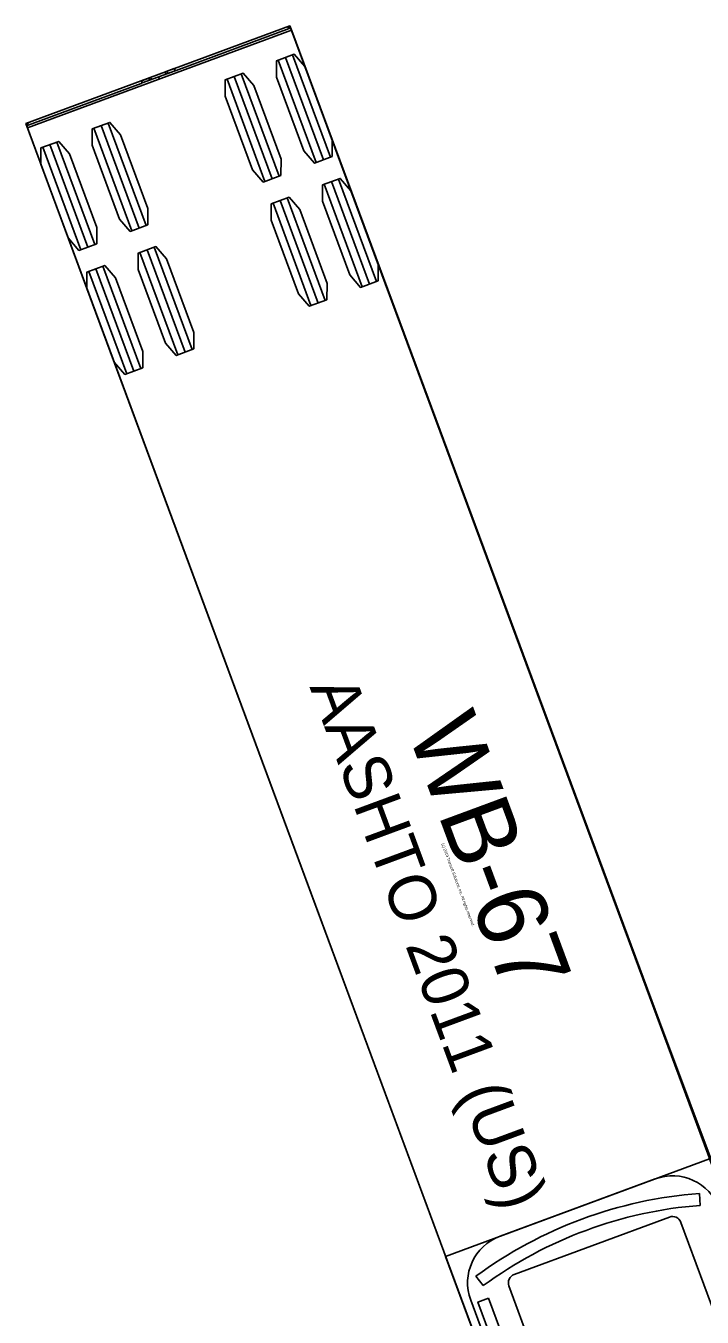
# Model space of a CAD drawing. Extents: x 1639988 to 1641860, y 841974 to 844187.
# Drawn here: x 1640169.79 to 1640190.21, y 844148.44 to 844187.46 of the extents above; entities that cross this region are included whole.
import ezdxf

# ---------------------------------------------------------------- set-up
doc = ezdxf.new("R2010")
doc.units = 0
for name, color, linetype in [('Scratch_Level_1', 7, 'Continuous'), ('Scratch_Level_2', 7, 'Continuous'), ('Scratch_Level_3', 7, 'Continuous'), ('Scratch_Level_4', 7, 'Continuous'), ('Scratch_Level_5', 7, 'Continuous'), ('Scratch_Level_6', 7, 'Continuous')]:
    doc.layers.add(name, color=color, linetype=linetype)

msp = doc.modelspace()

# ---------------------------------------------------------------- linework, layer by layer
at = {"layer": 'Scratch_Level_1'}
for p, q in [((1640169.838, 844184.375), (1640177.809, 844187.327)), ((1640178.556, 844183.329), (1640177.41, 844186.423)), ((1640178.771, 844183.408), (1640177.625, 844186.503)), ((1640178.986, 844183.488), (1640177.84, 844186.583)), ((1640174.048, 844186.01), (1640174.297, 844186.102)), ((1640177.224, 844182.835), (1640176.078, 844185.93)), ((1640177.439, 844182.915), (1640176.293, 844186.01)), ((1640173.301, 844185.733), (1640173.55, 844185.825)), ((1640173.799, 844185.917), (1640173.824, 844185.851)), ((1640177.009, 844182.756), (1640175.863, 844185.85)), ((1640173.207, 844181.348), (1640172.061, 844184.443)), ((1640173.422, 844181.428), (1640172.276, 844184.522)), ((1640172.992, 844181.269), (1640171.846, 844184.363)), ((1640171.445, 844180.696), (1640170.299, 844183.79)), ((1640171.66, 844180.775), (1640170.514, 844183.87)), ((1640171.875, 844180.855), (1640170.729, 844183.949)), ((1640180.375, 844179.737), (1640179.229, 844182.831)), ((1640179.945, 844179.578), (1640178.799, 844182.672)), ((1640180.16, 844179.657), (1640179.014, 844182.752)), ((1640178.398, 844179.005), (1640177.252, 844182.099)), ((1640178.613, 844179.084), (1640177.467, 844182.179)), ((1640178.828, 844179.164), (1640177.682, 844182.258)), ((1640174.381, 844177.517), (1640173.235, 844180.612)), ((1640174.596, 844177.597), (1640173.45, 844180.692)), ((1640174.811, 844177.677), (1640173.665, 844180.771)), ((1640173.049, 844177.024), (1640171.903, 844180.119)), ((1640173.263, 844177.104), (1640172.118, 844180.198)), ((1640172.834, 844176.944), (1640171.688, 844180.039))]:
    msp.add_line(p, q, dxfattribs=at)
for points in [[(1640240.487, 843983.993), (1640239.855, 843986.609), (1640227.577, 844027.488), (1640224.497, 844037.651), (1640222.927, 844042.709), (1640221.325, 844047.747), (1640219.681, 844052.761), (1640217.992, 844057.753), (1640216.257, 844062.717), (1640214.476, 844067.667), (1640212.652, 844072.609), (1640208.555, 844082.348), (1640206.537, 844087.24), (1640204.541, 844092.149), (1640202.565, 844097.075), (1640200.611, 844102.018), (1640198.676, 844106.976), (1640196.761, 844111.949), (1640192.983, 844121.925), (1640185.677, 844141.598), (1640169.789, 844184.508), (1640177.76, 844187.459), (1640177.815, 844187.311), (1640177.815, 844187.311)], [(1640169.834, 844184.449), (1640169.814, 844184.442), (1640169.839, 844184.376), (1640171.806, 844179.061), (1640188.192, 844134.805), (1640192.177, 844136.281), (1640196.163, 844137.757), (1640179.777, 844182.012), (1640177.808, 844187.327), (1640177.784, 844187.393), (1640177.764, 844187.385)], [(1640177.741, 844187.377), (1640177.74, 844187.377), (1640174.331, 844186.114), (1640174.297, 844186.102), (1640174.273, 844186.167), (1640174.271, 844186.167), (1640174.021, 844186.075)], [(1640177.815, 844187.311), (1640188.919, 844157.376), (1640192.648, 844147.427), (1640196.411, 844137.497), (1640200.22, 844127.592), (1640204.089, 844117.705), (1640228.263, 844057.033)], [(1640174.042, 844186.007), (1640173.553, 844185.826)], [(1640173.528, 844185.892), (1640173.278, 844185.8), (1640173.276, 844185.799), (1640173.301, 844185.733), (1640173.267, 844185.72), (1640169.858, 844184.458), (1640169.857, 844184.458)]]:
    msp.add_lwpolyline(points, dxfattribs=at)
for points in [[(1640179.039, 844183.508), (1640178.503, 844183.309), (1640178.181, 844183.682), (1640177.356, 844185.911), (1640177.357, 844186.404), (1640177.894, 844186.602), (1640178.216, 844186.229), (1640179.041, 844184.001)], [(1640177.492, 844182.935), (1640176.956, 844182.736), (1640176.634, 844183.109), (1640175.809, 844185.338), (1640175.81, 844185.831), (1640176.346, 844186.029), (1640176.668, 844185.656), (1640177.493, 844183.428)], [(1640173.475, 844181.447), (1640172.939, 844181.249), (1640172.617, 844181.622), (1640171.792, 844183.85), (1640171.793, 844184.343), (1640172.329, 844184.542), (1640172.651, 844184.169), (1640173.476, 844181.94)], [(1640171.928, 844180.874), (1640171.391, 844180.676), (1640171.069, 844181.049), (1640170.244, 844183.277), (1640170.246, 844183.771), (1640170.782, 844183.969), (1640171.104, 844183.596), (1640171.929, 844181.368)], [(1640180.428, 844179.756), (1640179.892, 844179.558), (1640179.57, 844179.931), (1640178.745, 844182.159), (1640178.746, 844182.653), (1640179.282, 844182.851), (1640179.605, 844182.478), (1640180.43, 844180.25)], [(1640178.881, 844179.184), (1640178.345, 844178.985), (1640178.023, 844179.358), (1640177.198, 844181.587), (1640177.199, 844182.08), (1640177.735, 844182.278), (1640178.057, 844181.905), (1640178.882, 844179.677)], [(1640174.864, 844177.696), (1640174.328, 844177.498), (1640174.006, 844177.871), (1640173.181, 844180.099), (1640173.182, 844180.592), (1640173.718, 844180.791), (1640174.04, 844180.418), (1640174.865, 844178.189)], [(1640173.317, 844177.123), (1640172.78, 844176.925), (1640172.458, 844177.298), (1640171.633, 844179.526), (1640171.635, 844180.019), (1640172.171, 844180.218), (1640172.493, 844179.845), (1640173.318, 844177.616)]]:
    msp.add_lwpolyline(points, close=True, dxfattribs=at)
for centre in [(1640177.741, 844187.413), (1640169.834, 844184.486)]:
    msp.add_circle(centre, 0.0266, dxfattribs=at)
for centre, radius, start, end in [((1640177.741, 844187.413), 0.0363, 309.395, 270.5563), ((1640174.033, 844186.042), 0.0352, 110.3428, 289.3432), ((1640174.034, 844186.042), 0.0353, 293.6537, 112.0033), ((1640173.54, 844185.859), 0.0354, 114.609, 286.7945), ((1640173.54, 844185.859), 0.0352, 291.2918, 110.2922), ((1640169.132, 844186.345), 2.022, 290.3175, 291.0013)]:
    msp.add_arc(centre, radius, start, end, dxfattribs=at)
at = {"layer": 'Scratch_Level_2'}
for p, q in [((1640169.838, 844184.375), (1640177.809, 844187.327)), ((1640178.556, 844183.329), (1640177.41, 844186.423)), ((1640178.771, 844183.408), (1640177.625, 844186.503)), ((1640178.986, 844183.488), (1640177.84, 844186.583)), ((1640174.048, 844186.01), (1640174.297, 844186.102)), ((1640177.224, 844182.835), (1640176.078, 844185.93)), ((1640177.439, 844182.915), (1640176.293, 844186.01)), ((1640173.301, 844185.733), (1640173.55, 844185.825)), ((1640173.799, 844185.917), (1640173.824, 844185.851)), ((1640177.009, 844182.756), (1640175.863, 844185.85)), ((1640173.207, 844181.348), (1640172.061, 844184.443)), ((1640173.422, 844181.428), (1640172.276, 844184.522)), ((1640172.992, 844181.269), (1640171.846, 844184.363)), ((1640171.445, 844180.696), (1640170.299, 844183.79)), ((1640171.66, 844180.775), (1640170.514, 844183.87)), ((1640171.875, 844180.855), (1640170.729, 844183.949)), ((1640180.375, 844179.737), (1640179.229, 844182.831)), ((1640179.945, 844179.578), (1640178.799, 844182.672)), ((1640180.16, 844179.657), (1640179.014, 844182.752)), ((1640178.398, 844179.005), (1640177.252, 844182.099)), ((1640178.613, 844179.084), (1640177.467, 844182.179)), ((1640178.828, 844179.164), (1640177.682, 844182.258)), ((1640174.381, 844177.517), (1640173.235, 844180.612)), ((1640174.596, 844177.597), (1640173.45, 844180.692)), ((1640174.811, 844177.677), (1640173.665, 844180.771)), ((1640173.049, 844177.024), (1640171.903, 844180.119)), ((1640173.263, 844177.104), (1640172.118, 844180.198)), ((1640172.834, 844176.944), (1640171.688, 844180.039))]:
    msp.add_line(p, q, dxfattribs=at)
for points in [[(1640240.487, 843983.993), (1640239.855, 843986.609), (1640227.577, 844027.488), (1640224.497, 844037.651), (1640222.927, 844042.709), (1640221.325, 844047.747), (1640219.681, 844052.761), (1640217.992, 844057.753), (1640216.257, 844062.717), (1640214.476, 844067.667), (1640212.652, 844072.609), (1640208.555, 844082.348), (1640206.537, 844087.24), (1640204.541, 844092.149), (1640202.565, 844097.075), (1640200.611, 844102.018), (1640198.676, 844106.976), (1640196.761, 844111.949), (1640192.983, 844121.925), (1640185.677, 844141.598), (1640169.789, 844184.508), (1640177.76, 844187.459), (1640177.811, 844187.321), (1640177.811, 844187.321)], [(1640169.834, 844184.449), (1640169.814, 844184.442), (1640169.839, 844184.376), (1640171.806, 844179.061), (1640188.192, 844134.805), (1640192.177, 844136.281), (1640196.163, 844137.757), (1640179.777, 844182.012), (1640177.808, 844187.327), (1640177.784, 844187.393), (1640177.764, 844187.385)], [(1640177.741, 844187.377), (1640177.74, 844187.377), (1640174.331, 844186.114), (1640174.297, 844186.102), (1640174.273, 844186.167), (1640174.271, 844186.167), (1640174.021, 844186.075)], [(1640177.811, 844187.321), (1640188.919, 844157.376), (1640192.648, 844147.427), (1640196.411, 844137.497), (1640200.22, 844127.592), (1640204.089, 844117.705), (1640228.263, 844057.033)], [(1640174.042, 844186.007), (1640173.553, 844185.826)], [(1640173.528, 844185.892), (1640173.278, 844185.8), (1640173.276, 844185.799), (1640173.301, 844185.733), (1640173.267, 844185.72), (1640169.858, 844184.458), (1640169.857, 844184.458)]]:
    msp.add_lwpolyline(points, dxfattribs=at)
for points in [[(1640179.039, 844183.508), (1640178.503, 844183.309), (1640178.181, 844183.682), (1640177.356, 844185.911), (1640177.357, 844186.404), (1640177.894, 844186.602), (1640178.216, 844186.229), (1640179.041, 844184.001)], [(1640177.492, 844182.935), (1640176.956, 844182.736), (1640176.634, 844183.109), (1640175.809, 844185.338), (1640175.81, 844185.831), (1640176.346, 844186.029), (1640176.668, 844185.656), (1640177.493, 844183.428)], [(1640173.475, 844181.447), (1640172.939, 844181.249), (1640172.617, 844181.622), (1640171.792, 844183.85), (1640171.793, 844184.343), (1640172.329, 844184.542), (1640172.651, 844184.169), (1640173.476, 844181.94)], [(1640171.928, 844180.874), (1640171.391, 844180.676), (1640171.069, 844181.049), (1640170.244, 844183.277), (1640170.246, 844183.771), (1640170.782, 844183.969), (1640171.104, 844183.596), (1640171.929, 844181.368)], [(1640180.428, 844179.756), (1640179.892, 844179.558), (1640179.57, 844179.931), (1640178.745, 844182.159), (1640178.746, 844182.653), (1640179.282, 844182.851), (1640179.605, 844182.478), (1640180.43, 844180.25)], [(1640178.881, 844179.184), (1640178.345, 844178.985), (1640178.023, 844179.358), (1640177.198, 844181.587), (1640177.199, 844182.08), (1640177.735, 844182.278), (1640178.057, 844181.905), (1640178.882, 844179.677)], [(1640174.864, 844177.696), (1640174.328, 844177.498), (1640174.006, 844177.871), (1640173.181, 844180.099), (1640173.182, 844180.592), (1640173.718, 844180.791), (1640174.04, 844180.418), (1640174.865, 844178.189)], [(1640173.317, 844177.123), (1640172.78, 844176.925), (1640172.458, 844177.298), (1640171.633, 844179.526), (1640171.635, 844180.019), (1640172.171, 844180.218), (1640172.493, 844179.845), (1640173.318, 844177.616)]]:
    msp.add_lwpolyline(points, close=True, dxfattribs=at)
for centre in [(1640177.741, 844187.413), (1640169.834, 844184.486)]:
    msp.add_circle(centre, 0.0266, dxfattribs=at)
for centre, radius, start, end in [((1640177.741, 844187.413), 0.0363, 309.395, 270.5563), ((1640174.033, 844186.042), 0.0352, 110.3428, 289.3432), ((1640174.034, 844186.042), 0.0353, 293.6537, 112.0033), ((1640173.54, 844185.859), 0.0354, 114.609, 286.7945), ((1640173.54, 844185.859), 0.0352, 291.2918, 110.2922), ((1640169.132, 844186.345), 2.022, 290.3175, 291.0013)]:
    msp.add_arc(centre, radius, start, end, dxfattribs=at)
at = {"layer": 'Scratch_Level_3'}
for p, q in [((1640169.838, 844184.375), (1640177.809, 844187.327)), ((1640178.556, 844183.329), (1640177.41, 844186.423)), ((1640178.771, 844183.408), (1640177.625, 844186.503)), ((1640178.986, 844183.488), (1640177.84, 844186.583)), ((1640174.048, 844186.01), (1640174.297, 844186.102)), ((1640177.224, 844182.835), (1640176.078, 844185.93)), ((1640177.439, 844182.915), (1640176.293, 844186.01)), ((1640173.301, 844185.733), (1640173.55, 844185.825)), ((1640173.799, 844185.917), (1640173.824, 844185.851)), ((1640177.009, 844182.756), (1640175.863, 844185.85)), ((1640173.207, 844181.348), (1640172.061, 844184.443)), ((1640173.422, 844181.428), (1640172.276, 844184.522)), ((1640172.992, 844181.269), (1640171.846, 844184.363)), ((1640171.445, 844180.696), (1640170.299, 844183.79)), ((1640171.66, 844180.775), (1640170.514, 844183.87)), ((1640171.875, 844180.855), (1640170.729, 844183.949)), ((1640180.375, 844179.737), (1640179.229, 844182.831)), ((1640179.945, 844179.578), (1640178.799, 844182.672)), ((1640180.16, 844179.657), (1640179.014, 844182.752)), ((1640178.398, 844179.005), (1640177.252, 844182.099)), ((1640178.613, 844179.084), (1640177.467, 844182.179)), ((1640178.828, 844179.164), (1640177.682, 844182.258)), ((1640174.381, 844177.517), (1640173.235, 844180.612)), ((1640174.596, 844177.597), (1640173.45, 844180.692)), ((1640174.811, 844177.677), (1640173.665, 844180.771)), ((1640173.049, 844177.024), (1640171.903, 844180.119)), ((1640173.263, 844177.104), (1640172.118, 844180.198)), ((1640172.834, 844176.944), (1640171.688, 844180.039))]:
    msp.add_line(p, q, dxfattribs=at)
for points in [[(1640240.487, 843983.993), (1640239.855, 843986.609), (1640227.577, 844027.488), (1640224.497, 844037.651), (1640222.927, 844042.709), (1640221.325, 844047.747), (1640219.681, 844052.761), (1640217.992, 844057.753), (1640216.257, 844062.717), (1640214.476, 844067.667), (1640212.652, 844072.609), (1640208.555, 844082.348), (1640206.537, 844087.24), (1640204.541, 844092.149), (1640202.565, 844097.075), (1640200.611, 844102.018), (1640198.676, 844106.976), (1640196.761, 844111.949), (1640192.983, 844121.925), (1640185.677, 844141.598), (1640169.789, 844184.508), (1640177.76, 844187.459), (1640177.809, 844187.326), (1640177.809, 844187.326)], [(1640169.834, 844184.449), (1640169.814, 844184.442), (1640169.839, 844184.376), (1640171.806, 844179.061), (1640188.192, 844134.805), (1640192.177, 844136.281), (1640196.163, 844137.757), (1640179.777, 844182.012), (1640177.808, 844187.327), (1640177.784, 844187.393), (1640177.764, 844187.385)], [(1640177.741, 844187.377), (1640177.74, 844187.377), (1640174.331, 844186.114), (1640174.297, 844186.102), (1640174.273, 844186.167), (1640174.271, 844186.167), (1640174.021, 844186.075)], [(1640177.809, 844187.326), (1640188.919, 844157.376), (1640192.648, 844147.427), (1640196.411, 844137.497), (1640200.22, 844127.592), (1640204.089, 844117.705), (1640228.263, 844057.033)], [(1640174.042, 844186.007), (1640173.553, 844185.826)], [(1640173.528, 844185.892), (1640173.278, 844185.8), (1640173.276, 844185.799), (1640173.301, 844185.733), (1640173.267, 844185.72), (1640169.858, 844184.458), (1640169.857, 844184.458)]]:
    msp.add_lwpolyline(points, dxfattribs=at)
for points in [[(1640179.039, 844183.508), (1640178.503, 844183.309), (1640178.181, 844183.682), (1640177.356, 844185.911), (1640177.357, 844186.404), (1640177.894, 844186.602), (1640178.216, 844186.229), (1640179.041, 844184.001)], [(1640177.492, 844182.935), (1640176.956, 844182.736), (1640176.634, 844183.109), (1640175.809, 844185.338), (1640175.81, 844185.831), (1640176.346, 844186.029), (1640176.668, 844185.656), (1640177.493, 844183.428)], [(1640173.475, 844181.447), (1640172.939, 844181.249), (1640172.617, 844181.622), (1640171.792, 844183.85), (1640171.793, 844184.343), (1640172.329, 844184.542), (1640172.651, 844184.169), (1640173.476, 844181.94)], [(1640171.928, 844180.874), (1640171.391, 844180.676), (1640171.069, 844181.049), (1640170.244, 844183.277), (1640170.246, 844183.771), (1640170.782, 844183.969), (1640171.104, 844183.596), (1640171.929, 844181.368)], [(1640180.428, 844179.756), (1640179.892, 844179.558), (1640179.57, 844179.931), (1640178.745, 844182.159), (1640178.746, 844182.653), (1640179.282, 844182.851), (1640179.605, 844182.478), (1640180.43, 844180.25)], [(1640178.881, 844179.184), (1640178.345, 844178.985), (1640178.023, 844179.358), (1640177.198, 844181.587), (1640177.199, 844182.08), (1640177.735, 844182.278), (1640178.057, 844181.905), (1640178.882, 844179.677)], [(1640174.864, 844177.696), (1640174.328, 844177.498), (1640174.006, 844177.871), (1640173.181, 844180.099), (1640173.182, 844180.592), (1640173.718, 844180.791), (1640174.04, 844180.418), (1640174.865, 844178.189)], [(1640173.317, 844177.123), (1640172.78, 844176.925), (1640172.458, 844177.298), (1640171.633, 844179.526), (1640171.635, 844180.019), (1640172.171, 844180.218), (1640172.493, 844179.845), (1640173.318, 844177.616)]]:
    msp.add_lwpolyline(points, close=True, dxfattribs=at)
for centre in [(1640177.741, 844187.413), (1640169.834, 844184.486)]:
    msp.add_circle(centre, 0.0266, dxfattribs=at)
for centre, radius, start, end in [((1640177.741, 844187.413), 0.0363, 309.395, 270.5563), ((1640174.033, 844186.042), 0.0352, 110.3428, 289.3432), ((1640174.034, 844186.042), 0.0353, 293.6537, 112.0033), ((1640173.54, 844185.859), 0.0354, 114.609, 286.7945), ((1640173.54, 844185.859), 0.0352, 291.2918, 110.2922), ((1640169.132, 844186.345), 2.022, 290.3175, 291.0013)]:
    msp.add_arc(centre, radius, start, end, dxfattribs=at)
at = {"layer": 'Scratch_Level_4'}
for p, q in [((1640189.218, 844151.469), (1640184.532, 844149.734)), ((1640202.216, 844117.144), (1640189.566, 844151.309)), ((1640184.372, 844149.386), (1640197.022, 844115.221))]:
    msp.add_line(p, q, dxfattribs=at)
for points in [[(1640207.65, 844083.889), (1640205.634, 844088.831), (1640203.645, 844093.787), (1640201.686, 844098.755), (1640199.758, 844103.733), (1640197.861, 844108.723), (1640182.463, 844150.279), (1640190.434, 844153.23), (1640190.54, 844152.943), (1640190.54, 844152.943)], [(1640188.791, 844152.622), (1640184.105, 844150.887)], [(1640190.126, 844152.182), (1640190.147, 844151.821)], [(1640183.598, 844149.396), (1640183.379, 844149.683)], [(1640183.219, 844148.959), (1640184.819, 844144.639), (1640184.633, 844144.418), (1640185.848, 844141.135), (1640186.133, 844141.088), (1640193.443, 844121.345), (1640193.313, 844120.973), (1640194.528, 844117.691), (1640194.869, 844117.493)]]:
    msp.add_lwpolyline(points, dxfattribs=at)
msp.add_lwpolyline([(1640183.76, 844149.019), (1640183.437, 844148.9), (1640185.506, 844143.31), (1640185.829, 844143.431)], close=True, dxfattribs=at)
for centre, radius, start, end in [((1640189.312, 844151.215), 1.5, 20.3175, 110.3175), ((1640191.116, 844139.147), 13.073, 94.3446, 126.2904), ((1640191.116, 844139.147), 12.711, 94.3748, 126.2603), ((1640189.312, 844151.215), 0.27, 20.3175, 110.3175), ((1640184.626, 844149.48), 1.5, 110.3175, 200.3175), ((1640184.626, 844149.48), 0.27, 110.3175, 200.3175)]:
    msp.add_arc(centre, radius, start, end, dxfattribs=at)
at = {"layer": 'Scratch_Level_5'}
for p, q in [((1640189.218, 844151.469), (1640184.532, 844149.734)), ((1640202.216, 844117.144), (1640189.566, 844151.309)), ((1640184.372, 844149.386), (1640197.022, 844115.221))]:
    msp.add_line(p, q, dxfattribs=at)
for points in [[(1640207.65, 844083.889), (1640205.634, 844088.831), (1640203.645, 844093.787), (1640201.686, 844098.755), (1640199.758, 844103.733), (1640197.861, 844108.723), (1640182.463, 844150.279), (1640190.434, 844153.23), (1640190.528, 844152.975), (1640190.528, 844152.975)], [(1640188.791, 844152.622), (1640184.105, 844150.887)], [(1640190.126, 844152.182), (1640190.147, 844151.821)], [(1640183.598, 844149.396), (1640183.379, 844149.683)], [(1640183.219, 844148.959), (1640184.819, 844144.639), (1640184.633, 844144.418), (1640185.848, 844141.135), (1640186.133, 844141.088), (1640193.443, 844121.345), (1640193.313, 844120.973), (1640194.528, 844117.691), (1640194.869, 844117.493)]]:
    msp.add_lwpolyline(points, dxfattribs=at)
msp.add_lwpolyline([(1640183.76, 844149.019), (1640183.437, 844148.9), (1640185.506, 844143.31), (1640185.829, 844143.431)], close=True, dxfattribs=at)
for centre, radius, start, end in [((1640189.312, 844151.215), 1.5, 20.3175, 110.3175), ((1640191.116, 844139.147), 13.073, 94.3446, 126.2904), ((1640191.116, 844139.147), 12.711, 94.3748, 126.2603), ((1640189.312, 844151.215), 0.27, 20.3175, 110.3175), ((1640184.626, 844149.48), 1.5, 110.3175, 200.3175), ((1640184.626, 844149.48), 0.27, 110.3175, 200.3175)]:
    msp.add_arc(centre, radius, start, end, dxfattribs=at)
at = {"layer": 'Scratch_Level_6'}
for p, q in [((1640189.218, 844151.469), (1640184.532, 844149.734)), ((1640202.216, 844117.144), (1640189.566, 844151.309)), ((1640184.372, 844149.386), (1640197.022, 844115.221))]:
    msp.add_line(p, q, dxfattribs=at)
for points in [[(1640207.65, 844083.889), (1640205.634, 844088.831), (1640203.645, 844093.787), (1640201.686, 844098.755), (1640199.758, 844103.733), (1640197.861, 844108.723), (1640182.463, 844150.279), (1640190.434, 844153.23), (1640190.518, 844153.001), (1640190.518, 844153.001)], [(1640188.791, 844152.622), (1640184.105, 844150.887)], [(1640190.126, 844152.182), (1640190.147, 844151.821)], [(1640183.598, 844149.396), (1640183.379, 844149.683)], [(1640183.219, 844148.959), (1640184.819, 844144.639), (1640184.633, 844144.418), (1640185.848, 844141.135), (1640186.133, 844141.088), (1640193.443, 844121.345), (1640193.313, 844120.973), (1640194.528, 844117.691), (1640194.869, 844117.493)]]:
    msp.add_lwpolyline(points, dxfattribs=at)
msp.add_lwpolyline([(1640183.76, 844149.019), (1640183.437, 844148.9), (1640185.506, 844143.31), (1640185.829, 844143.431)], close=True, dxfattribs=at)
for centre, radius, start, end in [((1640189.312, 844151.215), 1.5, 20.3175, 110.3175), ((1640191.116, 844139.147), 13.073, 94.3446, 126.2904), ((1640191.116, 844139.147), 12.711, 94.3748, 126.2603), ((1640189.312, 844151.215), 0.27, 20.3175, 110.3175), ((1640184.626, 844149.48), 1.5, 110.3175, 200.3175), ((1640184.626, 844149.48), 0.27, 110.3175, 200.3175)]:
    msp.add_arc(centre, radius, start, end, dxfattribs=at)

# ---------------------------------------------------------------- texts
at = {"layer": 'Scratch_Level_1'}
for s, height, p in [('AASHTO 2011 (US)', 1.41667, (1640178.35, 844167.485)), ('WB-67', 2.125, (1640181.291, 844166.173)), ('(c) 2019 Transoft Solutions, Inc. All rights reserved.', 0.085, (1640182.335, 844162.742))]:
    msp.add_text(s, height=height, rotation=290.3175, dxfattribs=at).set_placement(p)
at = {"layer": 'Scratch_Level_2'}
for s, height, p in [('AASHTO 2011 (US)', 1.41667, (1640178.35, 844167.485)), ('WB-67', 2.125, (1640181.291, 844166.173)), ('(c) 2019 Transoft Solutions, Inc. All rights reserved.', 0.085, (1640182.335, 844162.742))]:
    msp.add_text(s, height=height, rotation=290.3175, dxfattribs=at).set_placement(p)
at = {"layer": 'Scratch_Level_3'}
for s, height, p in [('AASHTO 2011 (US)', 1.41667, (1640178.35, 844167.485)), ('WB-67', 2.125, (1640181.291, 844166.173)), ('(c) 2019 Transoft Solutions, Inc. All rights reserved.', 0.085, (1640182.335, 844162.742))]:
    msp.add_text(s, height=height, rotation=290.3175, dxfattribs=at).set_placement(p)

doc.saveas('drawing.dxf')
